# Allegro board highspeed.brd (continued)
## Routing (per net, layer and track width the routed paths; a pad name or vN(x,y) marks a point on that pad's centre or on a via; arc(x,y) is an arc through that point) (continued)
RA<1>: length 164
  TOP w0.127: v1(71.63,67.46) 71.06,68.03 65.87,68.03 65.75,67.91 50.84,67.91 48.26,70.48 U7.60 ; U4.4 v1(79.38,102.49) ; U6.4 v1(102.87,102.49) ; U3.4 v1(102.87,63.12) ; U1.4 v1(79.38,75.82) ; U2.4 v1(79.38,86.11) ; U102.4 v1(102.87,86.11) ; U101.4 v1(102.87,75.82) 103.13,75.82 103.44,75.51 103.44,69.51 103.17,69.51 103.17,69.52 v1(102.87,69.52) ; v1(78.79,63.12) 79.07,63.12 79.38,62.81 U5.4
  BOTTOM w0.127: 78.81,86.11 78.81,78.63 79.38,78.06 v1(79.38,75.82) 79.38,75.14 78.79,74.56 78.79,67.46 ; 78.81,86.11 v1(79.38,86.11) ; 78.81,86.11 78.81,99.29 79.38,99.86 v1(79.38,102.49) 79.38,106.04 78.81,106.61 78.81,108.54 80.46,110.19 101.28,110.19 102.17,109.3 102.17,106.35 102.87,105.65 v1(102.87,102.49) v1(102.87,86.11) v1(102.87,75.82) ; v1(71.63,67.46) 71.63,67.46 78.79,67.46 ; 78.79,67.46 v1(78.79,63.12) ; v1(102.87,63.12) v1(102.87,69.52)
RA<2>: length 175.6
  TOP w0.127: v1(77.54,86.11) 77.8,86.11 78.11,86.41 U2.3 ; v1(53.31,68.86) 53.31,68.86 51.16,68.86 49.53,70.48 U7.61 ; U1.3 v1(78.11,75.82) ; U101.3 v1(101.6,75.82) ; v1(101.6,63.12) U3.3 101.6,60.24 101.35,59.99 85.53,59.99 85.02,60.5 85.02,63.43 84.77,63.69 78.5,63.69 78.11,63.29 U5.3 ; U6.3 101.6,101.68 101.47,101.8 v1(101.47,102.49) 100.58,103.38 97.01,103.38 95.86,104.53 78.04,104.53 76.27,102.75 76.27,99.81 76.39,99.69 77.54,99.69 78.11,100.25 U4.3 v1(78.11,102.49) ; U102.3 v1(101.6,86.11)
  BOTTOM w0.127: v1(101.47,102.49) 101.47,97.4 101.03,96.96 101.03,86.67 v1(101.6,86.11) v1(101.6,75.82) 101.03,75.25 101.03,63.69 v1(101.6,63.12) ; v1(53.31,68.86) 55.88,71.42 76.52,71.42 77.4,72.31 77.4,73.84 78.11,74.55 v1(78.11,75.82) 78.11,78.72 77.54,79.29 v1(77.54,86.11) 77.54,100.27 78.11,100.84 v1(78.11,102.49)
RA<3>: length 149.5
  TOP w0.127: U6.2 v1(100.33,102.49) 96.24,102.49 94.53,104.2 78.55,104.2 v1(76.84,102.49) 76.84,100.96 ; v1(99.76,75.82) 100.03,75.82 100.33,75.51 U101.2 ; v1(71.04,69.39) 69.49,70.94 v1(69.49,73.66) ; 76.84,61.6 v1(76.84,63.63) ; U102.2 100.33,86.41 100.03,86.11 v1(99.76,86.11) ; U7.62 50.8,71.91 51.61,72.72 v1(52.65,72.72) ; 76.84,87.63 76.84,88.91 v1(76.27,89.48) ; 76.84,74.3 v1(76.84,75.82) ; U3.2 v1(100.33,63.63)
  BOTTOM w0.127: v1(100.33,102.49) 99.76,101.92 v1(99.76,86.11) v1(99.76,75.82) 99.76,64.2 v1(100.33,63.63) ; v1(76.84,102.49) 76.27,101.92 v1(76.27,89.48) 76.27,75.82 ; 76.27,75.82 v1(76.84,75.82) ; 76.27,75.82 74.11,73.66 v1(69.49,73.66) 68.92,74.23 53.16,74.23 52.66,73.72 52.66,72.72 v1(52.65,72.72) ; v1(71.04,69.39) 71.04,67.18 72.95,65.27 75.19,65.27 v1(76.84,63.63)
RA<4>: length 159.4
  TOP w0.127: U6.32 v1(99.06,108.97) 97.48,107.38 76.58,107.38 75.56,108.4 v1(75.56,108.97) U4.32 ; U102.32 v1(99.06,98.68) ; v1(52.09,69.67) 52.07,69.7 U7.63 ; U3.32 v1(99.06,72.64) ; U101.32 v1(99.06,82.3) ; U5.32 75.56,71.83 75,72.4 74.52,72.4 74.25,72.14 v1(73.69,72.14) ; U2.32 v1(75.56,98.68) ; U1.32 v1(75.56,82.3)
  BOTTOM w0.127: 52.09,72.14 v1(52.09,69.67) ; 52.09,72.14 52.03,72.2 52.03,73.66 54.19,75.82 74.93,75.82 75.56,76.45 v1(75.56,82.3) v1(75.56,98.68) v1(75.56,108.97) ; 52.09,72.14 v1(73.69,72.14) ; v1(99.06,108.97) v1(99.06,98.68) v1(99.06,82.3) v1(99.06,72.64)
RA<5>: length 136.7
  TOP w0.127: 76.84,83.82 v1(76.84,82.3) ; 76.84,97.16 v1(76.84,98.68) ; U3.31 v1(100.33,72.64) ; v1(76.84,77.37) v1(100.33,77.37) ; U6.31 v1(100.33,107.77) ; U7.64 v1(53.34,73.58) ; 76.84,71.12 v1(76.84,72.64) ; U101.31 v1(100.33,82.3) ; 76.84,110.49 v1(76.84,108.28) ; U102.31 v1(100.33,98.68)
  BOTTOM w0.127: v1(76.84,108.28) 76.84,108.28 77.4,108.28 77.4,101.82 76.84,101.25 v1(76.84,98.68) v1(76.84,82.3) v1(76.84,77.37) 77.4,76.8 77.4,75.13 76.84,74.56 v1(76.84,72.64) 76.27,72.64 76.2,72.71 68.34,72.71 67.45,73.59 53.35,73.59 v1(53.34,73.58) ; v1(100.33,72.64) v1(100.33,77.37) v1(100.33,82.3) v1(100.33,98.68) 100.9,99.25 100.9,107.77 100.34,107.77 v1(100.33,107.77)
RA<6>: length 140.2
  TOP w0.127: U101.30 101.6,82.6 101.91,82.3 v1(102.17,82.3) ; v1(101.6,94.11) 78.13,94.11 v1(78.11,94.08) ; U7.65 v1(54.61,68.99) ; U1.30 v1(78.11,82.3) ; U2.30 v1(78.11,98.68) ; U5.30 v1(78.11,72.64) ; U102.30 v1(101.6,95.63) ; U6.30 v1(101.6,108.97) ; U3.30 v1(101.6,72.64) ; U4.30 v1(78.11,108.97)
  BOTTOM w0.127: v1(78.11,108.97) 78.11,104.98 78.67,104.41 78.67,100.51 78.11,99.94 v1(78.11,98.68) v1(78.11,94.08) v1(78.11,82.3) 78.11,81.04 78.43,80.72 78.43,77.16 78.67,76.92 78.67,75.3 78.43,75.05 78.43,73.7 78.11,73.38 v1(78.11,72.64) 78.11,72.04 76.84,70.77 55.75,70.77 54.61,69.62 v1(54.61,68.99) ; v1(101.6,108.97) 101.6,104.65 102.17,104.08 102.17,94.11 ; 102.17,94.11 v1(102.17,82.3) 102.17,73.21 v1(101.6,72.64) ; 102.17,94.11 v1(101.6,94.11) v1(101.6,95.63)
RA<7>: length 170.4
  TOP w0.127: 102.87,81.73 90.5,81.73 90.1,82.12 90.1,84.96 89.85,85.21 88.27,85.21 87.56,85.91 85.97,85.91 85.02,84.97 85.02,82.67 84.9,82.54 82.74,82.54 82.48,82.79 82.48,84.97 82.36,85.1 79.94,85.1 79.38,84.53 U1.29 v1(79.38,82.3) ; 102.87,81.73 U101.29 ; 102.87,81.73 103.07,81.73 103.45,81.35 v1(103.45,80.75) ; U7.66 v1(55.88,68.81) ; U5.29 v1(79.38,72.64) ; U102.29 102.87,95.63 v1(103.51,95.63) ; U2.29 v1(79.38,98.68) ; U3.29 v1(102.87,72.64) ; U6.29 v1(102.87,107.77) ; U4.29 v1(79.38,108.28)
  BOTTOM w0.127: v1(102.87,72.64) 103.45,73.23 v1(103.45,80.75) 103.51,80.8 v1(103.51,95.63) 103.51,107.77 102.88,107.77 v1(102.87,107.77) ; 79.94,98.68 79.94,85.11 79.38,84.54 v1(79.38,82.3) 79.38,79.61 79.94,79.05 79.94,74.48 79.38,73.91 v1(79.38,72.64) 79.38,62.9 78.98,62.5 73.36,62.5 70.7,65.17 70.7,65.74 68.41,68.03 67.63,68.03 65.47,65.87 65.47,63.34 64.58,62.45 58.53,62.45 57.89,63.08 57.89,67.41 56.5,68.81 55.88,68.81 v1(55.88,68.81) ; 79.94,98.68 v1(79.38,98.68) ; 79.94,98.68 79.94,108.28 79.38,108.28 v1(79.38,108.28)
RA<8>: length 155.5
  TOP w0.127: U6.28 v1(104.14,108.97) ; v1(104.14,82.3) U101.28 104.14,84.53 104.71,85.1 110.3,85.1 111.06,85.86 111.06,88.81 107.12,92.75 80.66,92.75 v1(80.64,92.76) ; U3.28 v1(104.14,72.64) ; U4.28 v1(80.64,108.97) ; U1.28 v1(80.64,82.3) ; U2.28 v1(80.64,98.68) ; U7.67 v1(57.15,69.67) ; U102.28 v1(104.14,98.68) ; v1(75.89,69.6) 79.83,69.6 80.64,70.41 U5.28 v1(80.64,72.64)
  BOTTOM w0.127: v1(75.89,69.6) 75.33,69.6 74.81,70.11 57.59,70.11 v1(57.15,69.67) ; 81.21,82.3 81.21,73.21 v1(80.64,72.64) ; 81.21,82.3 81.21,92.19 v1(80.64,92.76) v1(80.64,98.68) v1(80.64,108.97) ; 81.21,82.3 v1(80.64,82.3) ; v1(104.14,108.97) v1(104.14,98.68) v1(104.14,82.3) v1(104.14,72.64)
RA<9>: length 151.9
  TOP w0.127: v1(61.98,81.36) 61.99,81.35 87.31,81.35 v1(88.27,82.3) U1.22 ; U101.22 v1(111.76,82.3) ; U4.22 v1(88.27,107.95) 94.65,107.95 98.47,111.77 111.19,111.77 111.76,111.2 U6.22 v1(111.76,108.97) ; U2.22 88.27,98.37 88.57,98.68 v1(88.72,98.68) ; U102.22 v1(111.76,98.68) ; U3.22 v1(111.76,72.64) ; U5.22 v1(88.27,72.64) ; U7.69 v1(59.69,81.36)
  BOTTOM w0.127: 88.83,82.3 v1(88.27,82.3) ; 88.83,82.3 88.83,98.68 ; 88.83,82.3 88.83,73.21 v1(88.27,72.64) ; 88.83,98.68 v1(88.72,98.68) ; 88.83,98.68 88.83,107.38 v1(88.27,107.95) ; v1(111.76,108.97) 111.19,108.4 111.19,99.25 v1(111.76,98.68) v1(111.76,82.3) v1(111.76,72.64) ; v1(59.69,81.36) 59.7,81.35 61.97,81.35 v1(61.98,81.36)
RA<10>: length 146.4
  TOP w0.127: U102.21 v1(113.03,98.68) ; v1(89.53,108.97) U4.21 89.53,111.2 90.43,112.1 112.13,112.1 113.03,111.2 U6.21 v1(113.03,108.97) ; U7.70 60.96,72.96 66.67,78.67 68.97,78.67 69.48,79.18 69.48,80.49 69.73,80.75 v1(89.53,80.75) U1.21 ; U101.21 v1(113.03,82.3) ; U3.21 v1(113.03,72.64) ; U5.21 v1(89.53,72.64) ; U2.21 v1(89.53,98.68)
  BOTTOM w0.127: v1(89.53,108.97) v1(89.53,98.68) v1(89.53,80.75) v1(89.53,72.64) ; v1(113.03,108.97) v1(113.03,98.68) v1(113.03,82.3) v1(113.03,72.64)
RA<11>: length 145.1
  TOP w0.127: U3.20 v1(114.3,72.64) ; U1.20 v1(90.81,82.3) ; U101.20 v1(114.3,82.3) ; U6.20 v1(114.3,108.97) ; v1(72.29,68.81) 63.91,68.81 62.23,70.48 U7.71 ; v1(90.81,93.5) 113.49,93.5 v1(114.3,92.69) ; U102.20 v1(114.3,98.68) ; U2.20 v1(90.81,98.68) ; v1(76.48,68.81) 81.98,68.81 82.48,69.32 82.48,72.15 82.74,72.4 87.44,72.4 87.56,72.27 87.56,70.09 87.82,69.84 90.24,69.84 90.81,70.41 U5.20 v1(90.81,72.64) ; U4.20 v1(90.81,108.97)
  BOTTOM w0.127: v1(72.29,68.81) v1(76.48,68.81) ; v1(90.81,72.64) v1(90.81,82.3) v1(90.81,93.5) v1(90.81,98.68) v1(90.81,108.97) ; v1(114.3,72.64) v1(114.3,82.3) v1(114.3,92.69) v1(114.3,98.68) v1(114.3,108.97)
RA<12>: length 147.6
  TOP w0.127: v1(115.57,105.92) U6.19 115.57,111.2 114.35,112.42 89.76,112.42 88.97,111.63 88.97,108.65 89.22,108.4 91.06,108.4 91.37,108.71 v1(92.08,108.71) U4.19 ; U5.19 v1(92.08,72.64) ; v1(92.08,77.95) 75.34,77.95 74.2,76.81 74.2,75.04 v1(73.46,74.3) ; U1.19 v1(92.08,82.3) ; U2.19 v1(92.08,98.68) ; U101.19 v1(115.57,82.3) ; U102.19 v1(115.57,98.68) ; 67.87,74.3 v1(71.25,74.3) ; U3.19 v1(115.57,72.64)
  BOTTOM w0.127: 92.64,98.68 v1(92.08,98.68) ; 92.64,98.68 92.64,82.86 v1(92.08,82.3) v1(92.08,77.95) v1(92.08,72.64) ; 92.64,98.68 92.64,108.14 v1(92.08,108.71) ; v1(115.57,105.92) 116.14,105.35 116.14,99.25 v1(115.57,98.68) v1(115.57,82.3) v1(115.57,72.64) ; v1(71.25,74.3) v1(73.46,74.3)
RA<13>: length 139
  TOP w0.127: U6.18 v1(116.84,108.97) ; U3.18 v1(116.84,72.64) ; v1(104.72,81.33) 104.73,81.33 115.87,81.33 v1(116.84,82.3) U101.18 ; v1(104.72,77.95) v1(93.34,77.95) 92.78,78.52 74.67,78.52 73.77,77.63 71.46,77.63 69.4,75.56 U7.77 ; U4.18 v1(93.34,108.97) ; U102.18 v1(116.84,98.68) ; U1.18 v1(93.34,82.3) ; U5.18 v1(93.34,72.64) ; U2.18 v1(93.34,98.68)
  BOTTOM w0.127: v1(93.34,72.64) v1(93.34,77.95) v1(93.34,82.3) v1(93.34,98.68) v1(93.34,108.97) ; v1(104.73,77.95) 104.73,81.33 v1(104.72,81.33) ; v1(116.84,108.97) v1(116.84,98.68) v1(116.84,82.3) v1(116.84,72.64)
RA<14>: length 151.4
  TOP w0.127: v1(94.16,86.11) 93.54,86.11 93.34,86.3 U2.15 ; v1(117.68,89.15) 117.04,89.15 116.84,88.95 U102.15 ; v1(117.68,99.26) 117.09,99.26 116.84,99.52 U6.15 ; 116.84,75.92 113.28,79.48 v1(94.56,79.48) 94.55,79.49 71.1,79.49 70.47,78.85 70.47,78.72 68.58,76.83 U7.78 ; 116.84,75.92 U101.15 ; 116.84,75.92 v1(117.98,75.92) ; U5.15 v1(93.34,63.63) ; v1(94.16,102.49) 93.54,102.49 93.34,102.29 U4.15 ; U3.15 v1(116.84,63.63) ; v1(93.93,69.6) 93.93,75.45 93.8,75.57 93.34,75.57 U1.15
  BOTTOM w0.127: v1(93.34,63.63) 93.93,64.21 v1(93.93,69.6) 93.93,79.48 ; v1(116.84,63.63) 117.98,64.77 v1(117.98,75.92) 117.98,85.66 117.68,85.96 v1(117.68,89.15) v1(117.68,99.26) ; 93.93,79.48 v1(94.56,79.48) ; 93.93,79.48 93.93,82.55 94.16,82.78 v1(94.16,86.11) v1(94.16,102.49)
RA<15>: length 152.9
  TOP w0.127: v1(91.51,86.11) 91.77,86.11 92.08,86.41 U2.14 ; U101.14 115.57,75.51 115.27,75.82 v1(115,75.82) ; U5.14 v1(92.08,63.63) ; U7.79 67.16,78.1 66.59,77.54 66.59,75.12 66.84,74.86 71.56,74.86 71.82,74.61 71.82,72.21 76.57,67.46 v1(91.85,67.46) v1(115.57,67.46) ; v1(91.51,75.82) 91.77,75.82 92.08,75.51 U1.14 ; U4.14 v1(92.08,102.82) ; U102.14 115.57,86.41 115.27,86.11 v1(115,86.11) ; U3.14 v1(115.57,63.63) ; U6.14 v1(115.57,102.82)
  BOTTOM w0.127: v1(115.57,63.63) v1(115.57,67.46) 115,68.03 v1(115,75.82) v1(115,86.11) 115,102.82 115.57,102.82 v1(115.57,102.82) ; v1(92.08,63.63) 92.08,64.2 91.85,64.42 v1(91.85,67.46) 91.85,69.82 91.51,70.16 v1(91.51,75.82) v1(91.51,86.11) 91.51,102.82 92.07,102.82 v1(92.08,102.82)
RCS0: length 73.2
  TOP w0.127: 81.92,76.73 102.73,76.73 102.99,77 105.16,77 105.41,76.74 U101.6 ; 81.92,76.73 81.92,74.3 ; 81.92,76.73 v1(74.93,76.73) ; U7.48 v1(42.6,79.38)
  BOTTOM w0.127: v1(42.6,79.38) 60.48,79.38 63.64,76.21 74.41,76.21 v1(74.93,76.73)
RCS1: length 93.6
  TOP w0.127: U102.6 105.41,86.92 105.98,86.35 108.39,86.35 108.52,86.48 108.52,89.51 105.85,92.18 v1(81.92,92.18) ; v1(43.18,88.95) 43.18,79.12 42.16,78.1 U7.49 ; 81.92,87.63 v1(81.92,89.33) ; v1(81.92,91.03) 72.97,91.03 70.89,88.95 62.56,88.95 v1(62.56,88.95)
  BOTTOM w0.127: v1(43.18,88.95) 43.18,88.95 62.56,88.95 v1(62.56,88.95) ; v1(81.92,89.33) v1(81.92,91.03) v1(81.92,92.18)
RCS2: length 135.4
  TOP w0.127: v1(81.56,65.25) 64.37,65.25 62.97,63.86 62.97,63.34 62.08,62.45 56,62.45 55.2,63.24 55.2,63.81 53.8,65.2 38.88,65.2 36.72,67.36 36.72,75.45 38.1,76.83 U7.50 ; 81.92,100.96 81.92,101.68 83.87,103.63 v1(90.17,103.63) ; U3.6 v1(105.41,63.12)
  BOTTOM w0.127: v1(105.41,63.12) 104.84,62.55 92.26,62.55 89.84,64.96 89.84,66.23 ; 89.84,66.23 90.17,66.55 v1(90.17,103.63) ; 89.84,66.23 81.96,66.23 81.56,65.83 v1(81.56,65.25)
RCS3: length 125.4
  TOP w0.127: v1(98.37,65.66) v1(83.06,65.66) 82.45,65.66 82.21,65.9 39.21,65.9 37.94,67.17 37.94,67.92 38.73,68.71 39.94,68.71 41.21,69.98 41.21,73.88 39.52,75.56 U7.51 ; v1(98.37,104.22) 103.82,104.22 105.41,102.63 U6.6 ; 81.92,61.6 v1(81.92,63.12)
  BOTTOM w0.127: v1(98.37,104.22) 98.38,104.21 98.38,65.66 v1(98.37,65.66) ; v1(83.06,65.66) 83.06,64.26 v1(81.92,63.12)
RD<0>: length 94.1
  TOP w0.127: U7.81 61.8,80.64 61.41,81.04 61.41,88.71 64.07,91.37 70.22,91.37 73.49,94.65 82.2,94.65 v1(83.19,95.63) U2.26 ; U4.26 v1(83.19,108.97) ; v1(83.19,106.53) 104.01,106.53 106.68,109.19 U6.26 ; U1.26 v1(83.19,85.34)
  BOTTOM w0.127: v1(83.19,108.97) v1(83.19,106.53) 83.75,105.96 83.75,95.63 ; 83.75,95.63 83.75,85.91 v1(83.19,85.34) ; 83.75,95.63 v1(83.19,95.63)
RD<1>: length 76.6
  TOP w0.127: U6.23 110.49,109.12 107.31,105.94 v1(87,105.94) ; U7.82 70.79,81.91 71.43,82.56 74.09,82.56 74.92,81.73 86.2,81.73 87,82.52 v1(87,85.34) ; 87,97.16 87,95.94 87.3,95.63 v1(87.56,95.63) ; 87,110.49 v1(87,108.97)
  BOTTOM w0.127: v1(87,108.97) v1(87,105.94) 87.56,105.37 v1(87.56,95.63) 87.56,87.7 87,87.13 v1(87,85.34)
RD<2>: length 100
  TOP w0.127: 87,74.3 v1(87,76.15) ; 87,89.79 v1(92.08,89.79) ; 87,89.79 v1(87,89.15) 87,87.63 ; 87,89.79 86.73,90.05 75.98,90.05 73.95,88.02 73.95,84.84 72.3,83.19 U7.83 ; U6.10 110.49,102.26 111.28,103.06 113.98,103.06 114.87,102.17 114.87,95.95 113.98,95.06 92.83,95.06 92.64,95.25 v1(92.08,95.25) ; 87,100.96 v1(87,99.44)
  BOTTOM w0.127: v1(87,76.15) 86.43,76.15 86.43,88.58 v1(87,89.15) v1(87,99.44) ; v1(92.08,89.79) v1(92.08,95.25)
RD<3>: length 79.3
  TOP w0.127: v1(83.19,99.44) U4.7 83.19,101.68 84.57,103.06 90.48,103.06 91.37,102.17 91.37,99.94 91.63,99.69 106.11,99.69 106.68,100.25 U6.7 ; v1(83.19,89.33) U2.7 83.19,86.92 84.05,86.06 85.04,86.06 v1(85.04,86.05) ; U1.7 v1(83.19,76) ; U7.84 v1(70.26,84.45) ; v1(74.73,93.34) v1(83.19,93.34)
  BOTTOM w0.127: v1(74.73,93.34) 74.73,93.34 74.73,88.92 v1(70.26,84.45) ; v1(83.19,99.44) 82.62,98.87 82.62,94.92 83.19,94.35 v1(83.19,93.34) v1(83.19,89.33) ; v1(85.04,86.05) 85.04,84.77 83.19,82.92 v1(83.19,76)
RD<4>: length 105.5
  TOP w0.127: 105.98,72.64 105.98,77.58 104.71,78.85 84.09,78.85 83.93,79 71.46,79 v1(71.37,78.92) ; 105.98,72.64 105.98,69.35 105.58,68.95 84.07,68.95 83.19,69.84 U5.26 ; 105.98,72.64 v1(106.68,72.64) U3.26 ; U102.26 v1(106.68,95.63) ; U101.26 v1(106.68,82.3) ; U7.1 v1(69.39,85.72)
  BOTTOM w0.127: v1(69.39,85.72) 69.39,83.03 71.37,81.05 v1(71.37,78.92) ; v1(106.68,95.63) v1(106.68,82.3) v1(106.68,72.64)
RD<5>: length 115.1
  TOP w0.127: v1(72.16,83.87) 72.16,83.87 72.16,84.58 69.75,86.99 U7.2 ; 92.64,75.9 92.16,76.39 87.96,76.39 87.56,75.99 87.56,73.14 87.44,73.02 81.47,73.02 81.21,73.27 81.21,76.13 80.96,76.39 76.53,76.39 76.13,75.99 76.13,73.14 76.01,73.02 73.81,73.02 72.16,74.67 72.16,76.78 v1(72.16,76.78) ; 92.64,75.9 95.14,75.9 v1(95.15,75.89) ; 92.64,75.9 92.64,69.91 92.25,69.51 87.25,69.51 87,69.77 87,71.12 ; U101.23 v1(110.49,82.3) ; v1(95.15,68.22) 108.9,68.22 110.49,69.81 U3.23 v1(110.49,72.64) ; U102.23 v1(110.49,95.63)
  BOTTOM w0.127: v1(72.16,76.78) 72.16,76.78 72.16,83.87 v1(72.16,83.87) ; v1(95.15,68.22) v1(95.15,75.89) ; 111.06,82.3 111.06,73.21 v1(110.49,72.64) ; 111.06,82.3 v1(110.49,82.3) ; 111.06,82.3 111.06,95.06 v1(110.49,95.63)
RD<6>: length 104.2
  TOP w0.127: U101.10 v1(110.49,75.82) ; U7.3 71.69,88.27 73.8,90.38 92.39,90.38 92.64,90.13 92.64,86.43 93.53,85.54 109.92,85.54 v1(110.49,86.11) U102.10 ; 87,61.6 87,60.88 87.56,60.32 100.77,60.32 100.9,60.44 100.9,63.29 101.3,63.69 109.92,63.69 v1(110.49,63.12) U3.10
  BOTTOM w0.127: 109.92,75.82 109.92,85.54 v1(110.49,86.11) ; 109.92,75.82 109.92,63.69 v1(110.49,63.12) ; 109.92,75.82 v1(110.49,75.82)
RD<7>: length 99.6
  TOP w0.127: v1(106.68,63.12) U3.7 106.68,60.88 105.46,59.66 84.41,59.66 83.19,60.88 U5.7 ; U102.7 106.68,89.89 ; 106.68,89.89 104.97,91.6 71.78,91.6 69.71,89.53 U7.4 ; 106.68,89.89 v1(107.26,89.89) ; v1(107.25,75.82) 106.98,75.82 106.68,75.51 U101.7
  BOTTOM w0.127: v1(107.26,89.89) 107.27,89.89 107.27,76.4 107.25,76.39 v1(107.25,75.82) 107.25,63.69 v1(106.68,63.12)
RDY: length 33.9
  TOP w0.127: v1(41.28,59.16) 41.14,59.02 15.62,59.02 14.73,59.91 14.73,60.07 13.84,60.96 J3.50
  BOTTOM w0.127: 41.28,63.5 v1(41.28,59.16)
RESET: length 75.2
  TOP w0.127: U7.15 v1(62.23,98.73)
  BOTTOM w0.127: J3.53 13.75,69.63 18.68,69.63 21.35,72.3 21.35,80.59 22.5,81.75 22.5,86.9 24.74,89.14 24.74,91.91 24.97,92.15 24.97,94.52 30.05,99.6 61.36,99.6 v1(62.23,98.73)
RWE: length 174.4
  TOP w0.127: U5.11 v1(88.27,63.63) ; U101.11 111.76,75.72 v1(112.45,76.4) ; U7.57 44.45,67.72 44.7,67.46 v1(68.1,67.46) ; U4.11 v1(88.27,102.49) ; v1(112.45,89.26) 111.86,89.26 111.76,89.16 U102.11 ; U6.11 v1(111.76,102.49) ; U2.11 v1(88.27,86.11) ; U3.11 v1(111.76,63.12) ; U1.11 v1(88.27,75.82)
  BOTTOM w0.127: 87.7,75.82 v1(88.27,75.82) ; 87.7,75.82 87.7,85.54 v1(88.27,86.11) 88.27,92.18 88.15,92.29 88.15,101.81 88.27,101.92 v1(88.27,102.49) ; 87.7,75.82 83.02,71.15 82.64,71.15 80.99,69.49 80.99,64.45 81.21,64.23 81.21,62.55 81.54,62.22 ; v1(68.1,67.46) 68.1,66.78 73.3,61.57 80.89,61.57 81.54,62.22 ; 81.54,62.22 88.27,62.22 ; 88.27,62.22 110.86,62.22 v1(111.76,63.12) 112.45,63.8 v1(112.45,76.4) v1(112.45,89.26) 112.45,101.8 v1(111.76,102.49) ; 88.27,62.22 v1(88.27,63.63)
SEL: length 41.9
  TOP w0.127: U7.13 64.77,99.54 62.75,97.52 62.68,97.52 59.12,93.96 59.12,69.49 60.14,68.48 v1(61.29,68.48)
  BOTTOM w0.127: v1(61.29,68.48) 64.14,65.63 U17.14
UNNAMED_1_ACT574_I1_Q0: length 52.1
  TOP w0.127: U1_1.12 87.97,25.82 86.11,23.96 86.11,23.95 85.48,23.31 71.42,23.31 65.61,29.13 62.28,29.13 59,32.42 49.19,32.42 44.61,36.99 U20.19
UNNAMED_1_ACT574_I1_Q1: length 51.2
  TOP w0.127: U20.18 45.88,36.91 49.44,33.35 59.96,33.35 63.86,29.46 65.88,29.46 71.69,23.64 84.57,23.64 85.46,24.53 85.46,24.58 87.97,27.09 U1_1.13
UNNAMED_1_ACT574_I1_Q2: length 50.1
  TOP w0.127: U1_1.14 87.97,28.36 83.82,24.21 83.82,24.17 83.62,23.97 72.92,23.97 67.11,29.78 64.56,29.78 60.29,34.06 50.08,34.06 47.15,36.98 U20.17
UNNAMED_1_ACT574_I1_Q3: length 57.7
  TOP w0.127: U20.16 48.42,39.02 49.7,40.3 87.59,40.3 93.05,34.83 93.05,30.27 92.42,29.63 U1_1.15 88.29,29.63
UNNAMED_1_ACT574_I1_Q4: length 43.9
  TOP w0.127: U1_1.16 86.25,30.9 85.67,31.48 76.66,31.48 75.35,30.17 65.22,30.17 60.68,34.71 51.98,34.71 49.69,37 U20.15
UNNAMED_1_ACT574_I1_Q5: length 44
  TOP w0.127: U20.14 50.96,39.02 51.53,39.59 52.68,39.59 52.8,39.46 52.8,37.18 53.56,36.42 60.39,36.42 61.47,37.5 75.21,37.5 76.15,36.56 82.57,36.56 86.96,32.17 U1_1.17
UNNAMED_1_ACT574_I1_Q6: length 48.3
  TOP w0.127: U20.13 52.23,37.59 51.67,37.03 50.52,37.03 50.39,37.15 50.39,39.52 50.79,39.91 53.68,39.91 54.07,39.52 54.07,37.33 54.33,37.08 56.22,37.08 56.98,37.83 76.84,37.83 77.78,36.89 83.79,36.89 87.24,33.44 U1_1.18
UNNAMED_1_ACT574_I1_Q7: length 40.1
  TOP w0.127: U1_1.19 87.97,34.71 86.02,36.66 86.02,36.71 85.52,37.22 79.71,37.22 78.19,38.73 60.03,38.73 v1(60.02,38.73) ; U20.12 53.5,37 53.76,36.75 59.76,36.75 v1(60.02,37.01)
  BOTTOM w0.127: v1(60.02,37.01) 60.02,37.01 v1(60.02,38.73)
UNNAMED_1_ACT574_I2_Q0: length 57.4
  TOP w0.127: 89,5.12 87.59,5.12 82.89,9.82 82.89,15.69 82.05,16.53 78.13,16.53 75.79,18.88 48.89,18.88 44.07,23.7 U21.19
UNNAMED_1_ACT574_I2_Q1: length 57
  TOP w0.127: 45.34,25.07 45.34,23.7 49.66,19.39 82.78,19.39 83.54,18.62 83.54,10.45 87.61,6.39 89,6.39
UNNAMED_1_ACT574_I2_Q2: length 54.7
  TOP w0.127: U21.17 46.61,23.78 50.67,19.71 82.98,19.71 83.87,18.82 83.87,11.47 87.68,7.66 89,7.66
UNNAMED_1_ACT574_I2_Q3: length 59.2
  TOP w0.127: 88.59,8.93 90.75,8.93 90.9,9.08 90.9,18.38 86.95,22.33 65.66,22.33 61.31,26.68 48.78,26.68 47.88,25.78 47.88,25.07
UNNAMED_1_ACT574_I2_Q4: length 50
  TOP w0.127: U21.15 49.15,23.72 52.83,20.04 83.18,20.04 84.2,19.02 84.2,13.63 87.62,10.2 89,10.2
UNNAMED_1_ACT574_I2_Q5: length 51.9
  TOP w0.127: 50.42,25.07 50.42,25.78 50.99,26.35 60.41,26.35 65.08,21.68 85.8,21.68 90.4,17.08 90.4,11.88 89.99,11.47 88.59,11.47
UNNAMED_1_ACT574_I2_Q6: length 45.3
  TOP w0.127: 89,12.74 87.57,12.74 84.52,15.79 84.52,19.35 83.38,20.49 54.86,20.49 51.69,23.67 U21.13
UNNAMED_1_ACT574_I2_Q7: length 43.2
  TOP w0.127: 89,14.01 87.62,14.01 84.95,16.68 84.95,19.62 83.55,21.02 55.63,21.02 52.96,23.69 U21.12
UNNAMED_1_CAP_I33_A_1: length 12.8
  TOP w0.127: 74.37,32.17 74.37,35.33 L1_1.2 ; 74.37,32.17 73.78,31.58 C2_1.1 ; 74.37,32.17 U1_1.4
UNNAMED_1_CAP_I33_A_2: length 12.8
  TOP w0.127: C2_2.1 74.08,10.88 74.67,11.47 ; L1_2.2 74.67,14.63 74.67,11.47 ; 74.67,11.47 U1_2.4
UNNAMED_1_CAP_I67_A: length 2.2
  TOP w0.127: C21.1 R11.2
UNNAMED_1_CAP_I68_A: length 2.2
  TOP w0.127: C22.1 R12.2
UNNAMED_1_CAP_I69_A: length 2.2
  TOP w0.127: C23.1 R13.2
UNNAMED_1_CAP_I70_A: length 2.2
  TOP w0.127: C24.1 R14.2
UNNAMED_1_CAP_I71_A: length 2.2
  TOP w0.127: C25.1 R15.2
UNNAMED_1_CAP_I72_A: length 2.2
  TOP w0.127: C26.1 R16.2
UNNAMED_1_CAP_I73_A: length 2.2
  TOP w0.127: C27.1 R17.2
UNNAMED_1_CAP_I74_A: length 2.2
  TOP w0.127: C28.1 R18.2
UNNAMED_1_DG419_I6_D_1: length 10.5
  TOP w0.5: U2_1.1 103.41,33.69 99.6,29.88
UNNAMED_1_DG419_I6_D_2: length 10.5
  TOP w0.5: 108.82,12.98 103.7,12.98 U3_2.2
UNNAMED_1_DG419_I6_S1_1: length 6.4
  TOP w0.127: R2_1.2 109.91,27.64 110.88,28.61 110.88,30.38 108.84,32.41 U2_1.2
UNNAMED_1_DG419_I6_S1_2: length 6.4
  TOP w0.127: R2_2.2 110.21,6.94 111.18,7.91 111.18,9.68 109.14,11.71 108.82,11.71
UNNAMED_1_DG419_I6_S2_1: length 3.5
  TOP w0.127: R1_1.2 116.44,32.57 115.32,33.69 U2_1.8
UNNAMED_1_DG419_I6_S2_2: length 3.5
  TOP w0.127: R1_2.2 116.74,11.87 115.62,12.98 U2_2.8
UNNAMED_1_DG419_I6_VL_1: length 67.7
  TOP w0.127: U1_1.8 77.19,27.09 77,27.28 ; 78.13,30.9 77.25,30.9 77,30.65 77,27.28 ; 78.13,30.9 77.81,30.57 77.81,29.27 78.13,28.94 90.14,28.94 91.2,27.88 91.2,25.77 94.12,22.85 114.34,22.85 115.86,24.38 115.86,28.66 ; 78.13,30.9 U1_1.5 ; 115.86,28.66 115.53,28.99 113.48,28.99 ; 115.86,28.66 116.5,29.3 R1_1.1 ; 77,27.28 L2_1.2 ; 113.48,29.88 113.48,28.99 ; 113.48,28.99 113.48,28.92 112.2,27.64 R2_1.1
UNNAMED_1_DG419_I6_VL_2: length 64.2
  TOP w0.127: 77.5,8.28 77.5,6.58 ; 77.5,8.28 77.54,8.24 80.63,8.24 80.64,8.23 82.35,8.23 83,7.58 83,5.38 86.11,2.28 109.76,2.28 115.1,7.61 115.1,8.29 ; 77.5,8.28 77.5,10.08 77.62,10.2 U1_2.5 ; 77.5,6.58 77.69,6.39 U1_2.8 ; 77.5,6.58 L2_2.2 ; 115,8.62 115,8.92 114.75,9.18 U2_2.5 ; 115,8.62 115.1,8.52 115.1,8.29 ; 115,8.62 115,8.4 113.48,6.88 R2_2.1 ; R1_2.1 116.8,8.49 116.6,8.29 115.1,8.29
UNNAMED_1_TLC5602_I31_AOUT_1: length 19.6
  TOP w0.127: v1(92.2,30.23) 87.24,30.23 86.64,29.63 U1_1.6
  BOTTOM w0.127: v1(92.2,30.23) 93.8,30.23 95.24,31.67 96.75,31.67 U3_1.3
UNNAMED_1_TLC5602_I31_AOUT_2: length 28.9
  TOP w0.127: v1(94.49,3.17) 86.88,3.17 84.4,5.65 84.4,7.48 82.95,8.93 U1_2.6
  BOTTOM w0.127: v1(94.49,3.17) 94.49,9.07 96.39,10.97 97.05,10.97 U3_2.3
UNNAMED_2_EPF8282A_I1_VCLKC: length 57.7
  TOP w0.127: v1(41.5,90.78) 41.5,91.95 40.11,93.34 U7.37
  BOTTOM w0.127: v1(41.5,90.78) 41.5,78.87 42.01,78.36 42.11,78.36 43.7,76.78 43.7,67.86 44.84,66.71 47.53,66.71 50.32,63.93 50.32,47.03 51.91,45.44 52.96,45.44 R5.1
UNNAMED_3_ACT574_I6_Q0: length 7.9
  TOP w0.127: R20.1 148.88,83.86 U24.19
UNNAMED_3_ACT574_I6_Q1: length 7.6
  TOP w0.127: 144.74,82.59 149.64,82.59 R21.1
UNNAMED_3_ACT574_I6_Q2: length 7.3
  TOP w0.127: R22.1 150.4,81.32 U24.17
UNNAMED_3_ACT574_I6_Q3: length 7
  TOP w0.127: R23.1 151.16,80.05 U24.16
UNNAMED_3_ACT574_I6_Q4: length 7
  TOP w0.127: R24.1 151.16,78.78 U24.15
UNNAMED_3_ACT574_I6_Q5: length 7.3
  TOP w0.127: R25.1 150.4,77.52 144.74,77.52
UNNAMED_3_ACT574_I6_Q6: length 7.6
  TOP w0.127: U24.13 148.67,76.24 150.58,74.34 R26.1
UNNAMED_3_ACT574_I6_Q7: length 7.9
  TOP w0.127: U24.12 148.88,74.97 R27.1
UNNAMED_3_MN3102_I89_OUT: length 3.5
  TOP w0.127: U22.7 97.23,51.31 R19.1
V+12: length 261.7
  TOP w0.4: v1(94.08,23.75) 94.07,23.76 94.07,34.75 95.6,36.28 C3_1.1 95.6,37.92 91.79,41.73 57.41,41.73 54.86,44.29 41.71,44.29 38.97,41.55 38.97,31.7 32.49,25.23 17.63,25.23 16.11,26.75 v1(2.21,26.75) ; 98.1,3.65 103.11,3.65 106.16,6.7 106.16,6.82 108.51,9.18 108.82,9.18 ; 98.1,3.65 U3_2.7 ; 98.1,3.65 95.87,3.65 94.37,5.15 94.37,14.05 95.9,15.58 C3_2.1 95.9,15.98 94.92,16.96 94.92,19.38 v1(95.63,20.09) ; U3_1.7 98.7,24.64 103.02,24.64 106.42,28.04 106.42,28.09 108.21,29.88 108.52,29.88 ; J3.63 J3.64
  BOTTOM w0.4: 95.63,23.42 97.17,23.42 97.8,24.06 U3_1.7 ; 95.63,23.42 v1(95.63,20.09) ; 95.63,23.42 95.3,23.75 v1(94.08,23.75) ; v1(2.21,26.75) 2.21,90.85 6.53,95.17 11.35,95.17 J3.64
VCLKA: length 148.4
  TOP w0.127: 89,3.85 90.67,3.85 91.6,4.78 91.6,20.75 89.14,23.21 ; v1(55.37,39.78) 54.77,39.78 U20.11 ; v1(56.31,28.68) 63.52,28.68 65.17,27.02 65.17,26.95 69.23,22.89 88.81,22.89 89.14,23.21 ; v1(55.32,69.55) 55.31,69.56 55.31,79.69 44.97,90.03 44.97,101.4 44.46,101.91 43.19,101.91 42.43,101.15 42.43,99.06 40.52,97.16 U7.34 ; 89.14,23.21 89.14,24.11 U1_1.11
  BOTTOM w0.127: v1(55.32,69.55) 55.31,69.53 55.31,40.36 55.37,40.3 v1(55.37,39.78) 56.32,38.83 56.32,28.68 v1(56.31,28.68)
VCLKC: length 32.5
  TOP w0.127: U21.11 v1(54.23,23.16)
  BOTTOM w0.127: v1(54.23,23.16) 52.74,24.65 52.74,35.15 52.44,35.45 52.44,41.43 54.36,43.36 54.36,49.58 53.97,49.98 53.36,49.98 52.96,49.58 R5.2
VD<0>: length 327
  TOP w0.127: U19.2 v1(44.07,41.02) ; U20.2 44.61,30.62 v1(44.6,30.63) ; U21.2 v1(44.07,17.96) 44.06,17.97 42.55,17.97 40.77,16.19 R18.1 ; v1(69.98,92.28) 72.68,94.98 80.2,94.98 81.21,95.99 81.21,98.18 81.47,98.44 83.63,98.44 83.75,98.31 83.75,95.31 84.39,94.68 117.47,94.68 120.64,91.5 120.64,91.48 128.26,83.86 U24.2 139.49,83.86 143.19,87.56 152.38,87.56 152.5,87.43 152.5,62.14 148.73,58.36 148.73,38.35 157.42,29.65 189.76,29.65 195.09,24.32 195.09,23.09 194.53,22.52 U25.2 ; U7.39 v1(37.29,90.8)
  BOTTOM w0.127: 44.3,30.63 v1(44.6,30.63) ; 44.3,30.63 44.3,18.76 44.07,18.53 v1(44.07,17.96) ; 44.3,30.63 44.03,30.63 44.03,40.42 44.07,40.45 v1(44.07,41.02) 42.85,42.24 41.75,42.24 36.16,47.83 36.16,89.68 v1(37.29,90.8) 37.86,91.37 37.86,91.39 38.75,92.27 69.97,92.27 v1(69.98,92.28)
VD<1>: length 285.6
  TOP w0.127: 45.34,15.88 v1(45.34,17.4) 44.77,17.4 44.64,17.27 44.64,14.75 44.24,14.35 43.72,14.35 42.93,13.56 R17.1 ; 45.34,42.55 v1(45.34,41.02) ; v1(70.05,80.16) 121.32,80.16 123.89,82.73 134.12,82.73 134.26,82.59 143.07,82.59 143.07,82.25 v1(143.08,82.24) ; v1(45.87,30.66) 45.88,30.65 U20.3 ; v1(188.26,21.51) 188.26,21.25 U25.3 ; U7.40 v1(40.33,89.53)
  BOTTOM w0.127: v1(70.05,80.16) 64.44,85.78 64.44,88 61.14,91.3 41.22,91.3 40.33,90.41 v1(40.33,89.53) 38.51,87.71 38.51,76.22 39.79,74.94 39.79,49.44 45.34,43.89 v1(45.34,41.02) 45.34,36.13 45.57,35.9 45.57,30.66 ; 45.57,30.66 v1(45.87,30.66) ; 45.57,30.66 45.57,30.06 45.34,29.83 v1(45.34,17.4) ; v1(143.08,82.24) 159.75,65.57 159.75,55.12 188.26,26.61 v1(188.26,21.51)
VD<2>: length 292
  TOP w0.127: v1(187.1,20.24) 187.1,19.98 U25.4 ; v1(40.36,59.97) 40.37,59.98 65.21,59.98 65.85,59.33 119.36,59.33 124.31,64.29 124.31,74.58 124.87,75.14 124.87,75.62 124.63,75.86 124.63,76.25 130.78,82.41 132.56,82.41 133.65,81.32 U24.4 140.49,81.32 v1(143.03,78.79) ; U21.4 46.61,14.35 ; 46.61,14.35 45.88,14.35 45.08,13.56 R16.1 ; 46.61,14.35 v1(47.14,14.35) ; v1(47.14,30.63) 47.15,30.62 U20.4 ; U7.41 v1(40.92,88.27) ; U19.4 v1(46.61,41.02)
  BOTTOM w0.127: v1(47.14,14.35) v1(47.14,30.63) 47.14,35.19 46.61,35.72 v1(46.61,41.02) 46.61,48.01 42.33,52.29 42.33,56.93 40.36,58.89 v1(40.36,59.97) 40.22,60.11 40.22,79.1 40.92,79.79 v1(40.92,88.27) ; v1(187.1,20.24) 187.1,26.28 159.43,53.95 159.43,62.39 v1(143.03,78.79)
VD<3>: length 306.5
  TOP w0.127: U24.5 134.02,80.05 v1(134.01,80.06) ; U7.42 v1(37.29,86.99) ; v1(39.17,66.9) 39.76,66.31 115.73,66.31 122.08,72.66 122.08,76.59 123.19,77.7 123.19,77.97 124,78.78 v1(125.1,78.78) ; v1(139.19,54.56) 139.19,54.29 139.5,53.98 U8.4 141.53,53.98 143.08,52.44 143.08,39.65 155.78,26.95 177.68,26.95 185.92,18.71 U25.5 ; 47.88,42.55 v1(47.88,40.87) ; R15.1 47.37,13.41 47.88,13.92 v1(47.88,17.73) ; U20.5 48.42,30.62 v1(48.41,30.63) 41.66,37.39 v1(41.66,43.16)
  BOTTOM w0.127: v1(47.88,17.73) 48.18,17.73 48.18,17.73 48.41,17.73 v1(48.41,30.63) 48.41,39.77 47.88,40.3 v1(47.88,40.87) ; v1(37.29,86.99) 38.18,86.1 38.18,72.47 39.17,71.49 v1(39.17,66.9) 37.68,65.42 37.68,47.13 v1(41.66,43.16) ; v1(125.1,78.78) 126.38,80.06 v1(134.01,80.06) 134.01,76.81 134.19,76.62 134.19,75.88 134.01,75.69 134.01,59 138.45,54.56 139.19,54.56 v1(139.19,54.56)
VD<4>: length 313.9
  TOP w0.127: v1(123.34,64.21) 76.41,64.21 73.85,61.65 v1(54.23,61.65) ; U21.6 49.15,14.35 ; 49.15,14.35 v1(49.68,14.35) ; 49.15,14.35 49.15,13.79 49.53,13.41 R14.1 ; v1(139.19,55.47) 139.19,55.47 139.53,55.47 139.53,55.26 U8.3 141.53,55.26 144.06,52.72 144.06,41.05 156.76,28.35 177.89,28.35 186.95,19.28 194.97,19.28 195.09,19.16 195.09,18.01 194.53,17.45 U25.6 ; U24.6 136.82,78.78 137.04,78.56 v1(137.74,78.56) ; U19.6 v1(49.15,41.02) ; U7.43 39.52,85.72 41.81,88.02 41.81,88.5 42.83,89.52 43.5,89.52 43.75,89.27 43.75,77.82 45.03,76.53 v1(45.03,68.05) ; U20.6 49.69,30.62 v1(49.68,30.63)
  BOTTOM w0.127: v1(123.34,64.21) 119.7,67.85 119.7,77.4 123.26,80.96 135.34,80.96 v1(137.74,78.56) 137.74,56.27 138.53,55.47 139.19,55.47 v1(139.19,55.47) ; v1(49.68,14.35) v1(49.68,30.63) 49.72,30.67 49.72,40.45 v1(49.15,41.02) 51.93,43.8 52.28,43.8 53.94,45.45 53.94,47.2 53.54,47.59 52.16,47.59 51.66,48.1 51.66,51.59 52.81,52.75 52.81,60.87 ; 52.81,60.87 53.46,60.87 v1(54.23,61.65) ; 52.81,60.87 52.49,61.2 52.49,64.7 49.14,68.05 45.03,68.05 v1(45.03,68.05)
VD<5>: length 306.2
  TOP w0.127: 50.42,15.88 50.42,14.66 50.72,14.35 v1(50.95,14.35) 51.56,13.74 R13.1 ; v1(50.7,40.97) 50.42,41.25 50.42,42.55 ; v1(38.51,67.49) 41.72,67.49 42.33,66.88 v1(57.3,66.88) 57.31,66.88 115.79,66.88 121.51,72.59 121.51,77.16 v1(121.51,77.16) ; 135.54,77.52 132.71,77.52 132.71,77.47 132.71,77.47 v1(132.71,77.16) ; v1(183.87,16.43) 183.88,16.42 183.88,16.18 193.81,16.18 ; U20.7 50.96,30.63 v1(50.95,30.63) 52.12,31.8 57.45,31.8 v1(57.45,31.8) ; U7.44 v1(37.29,84.45)
  BOTTOM w0.127: v1(50.7,40.97) 50.71,40.96 50.71,30.87 v1(50.95,30.63) v1(50.95,14.35) ; v1(183.87,16.43) 183.87,20.51 182.92,21.46 182.92,21.5 182.58,21.83 182.55,21.83 177.1,27.28 167,27.28 150.3,43.98 138.7,43.98 132.8,49.88 132.8,74.95 133.87,76.02 133.87,76.49 133.19,77.16 v1(132.71,77.16) 132.71,77.16 121.52,77.16 v1(121.51,77.16) ; v1(57.3,66.88) 57.3,65.66 57.57,65.4 57.57,31.91 v1(57.45,31.8) ; v1(37.29,84.45) 37.86,83.89 37.86,67.49 v1(38.51,67.49)
VD<6>: length 301.3
  TOP w0.127: U24.8 133.3,76.24 v1(133.3,76.25) ; R12.1 53.72,13.63 53.32,14.02 53.08,14.02 52.29,14.82 v1(52.29,17.4) 51.99,17.4 51.69,17.09 U21.8 ; U7.45 v1(36.73,83.19) ; v1(52.22,30.63) 52.23,30.62 U20.8 ; v1(182.35,21.26) 182.35,17.06 184.51,14.91 U25.8 ; v1(51.69,40.97) U19.8 51.69,43.26 51.12,43.83 47.42,43.83 47.29,43.7 47.29,40.29 v1(47.3,40.28) ; v1(36.73,62.23) v1(42.67,62.23) 54.82,62.23 54.92,62.12 73.52,62.12 76.07,64.67 114.62,64.67 122.75,72.8 122.75,74.25 124.06,75.56 124.12,75.56 v1(124.3,75.38)
  BOTTOM w0.127: v1(36.73,83.19) 36.72,83.17 36.72,62.24 v1(36.73,62.23) ; v1(47.3,40.28) 47.29,40.29 47.29,50.95 46.15,52.09 46.1,52.09 42.67,55.52 v1(42.67,62.23) ; v1(52.29,17.4) 52.29,17.97 52.22,18.03 v1(52.22,30.63) 52.22,32.9 51.69,33.43 v1(51.69,40.97) ; v1(124.3,75.38) 125.17,76.24 133.29,76.24 v1(133.3,76.25) 133.3,75.91 132.47,75.08 132.47,49.74 139.14,43.08 149.6,43.08 165.73,26.95 176.96,26.95 182.35,21.57 v1(182.35,21.26)
VD<7>: length 301.3
  TOP w0.127: U21.9 52.96,15.16 53.56,14.56 54.98,14.56 v1(55.88,13.66) R11.1 ; v1(45.26,58.83) 45.52,58.57 62.53,58.57 62.65,58.45 ; 62.65,58.45 124.71,58.45 v1(124.71,58.45) ; 62.65,58.45 62.65,54.63 v1(62.66,54.61) ; v1(165.6,22.28) 165.6,22.18 174.14,13.64 193.81,13.64 ; v1(42.32,77.42) 37.78,77.42 37.53,77.67 37.53,81.35 38.1,81.91 U7.46 ; v1(53.49,30.63) 53.5,30.62 U20.9 ; U19.9 v1(52.96,40.97) ; U24.9 132.75,74.97 132.54,75.18 v1(130.2,75.18)
  BOTTOM w0.127: 55.88,28.14 55.4,28.14 53.49,30.05 v1(53.49,30.63) 53.49,37.22 52.96,37.75 v1(52.96,40.97) ; 55.88,28.14 v1(55.88,13.66) ; 55.88,28.14 56.52,28.14 58.68,30.3 58.68,50.63 v1(62.66,54.61) ; v1(165.6,22.28) 150.2,37.68 150.2,39.28 148.2,41.28 130.2,41.28 128.68,42.8 128.68,58.45 ; 128.68,58.45 124.72,58.45 v1(124.71,58.45) ; 128.68,58.45 128.68,74.26 129.6,75.18 v1(130.2,75.18) ; v1(42.32,77.42) 42.33,77.41 42.33,66.47 43.6,65.2 43.61,65.2 45.26,63.55 45.26,58.83 v1(45.26,58.83)
VREF: length 31.4
  TOP w0.4: v1(61.62,18.29) 63.39,18.29 L1_2.1 ; v1(60.35,35.31) 64.23,35.31 L1_1.1 ; R10.1 61.62,22.08 v1(61.62,23.49)
  BOTTOM w0.4: v1(60.35,35.31) 60.36,35.3 60.36,24 60.86,23.49 v1(61.62,23.49) v1(61.62,18.29)
WAIT: length 57.6
  TOP w0.127: v1(28.37,75.51) 32.88,75.51 34.15,76.78 34.15,95.12 37.45,98.42 U7.33
  BOTTOM w0.127: J3.51 27.11,63.5 28.38,64.77 28.38,75.5 v1(28.37,75.51)
WSTAT: length 27.7
  TOP w0.127: U19.11 54.23,52.45 53.42,53.26 v1(47.57,53.26) ; U7.56 v1(43.18,69.67)
  BOTTOM w0.127: v1(43.18,69.67) 43.18,67.76 45.08,65.86 45.54,65.86 47.57,63.83 v1(47.57,53.26)

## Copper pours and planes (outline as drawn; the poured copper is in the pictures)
AGND on BOTTOM: 63.6,25.38 63.6,36.38 67.6,40.38 103.6,40.38 108.6,35.38 108.6,24.38 107.6,23.38 103.6,23.38 103.6,30.38 101.6,32.38 93.6,32.38 91.6,30.38 91.6,26.38 87.6,22.38 66.6,22.38
AGND on BOTTOM: 63.9,4.68 63.9,15.68 67.9,19.68 103.9,19.68 108.9,14.68 108.9,3.68 107.9,2.68 103.9,2.68 103.9,9.68 101.9,11.68 93.9,11.68 91.9,9.68 91.9,5.68 87.9,1.68 66.9,1.68
GND on GND (solid shape): 120.9,21.08 119.5,21.08 119.5,22.88 120.9,22.88
GND on GND: 23.65,1.9 23.5,2.06 23.5,6.99 2.06,6.99 1.9,7.14 1.9,107.16 2.06,107.31 23.5,107.31 23.5,112.24 23.65,112.39 262.25,112.39 263.52,111.12 263.52,3.17 261.62,1.27 93.34,1.27 93.34,1.9 ; 1 cut-out
GND_EARTH on GND (solid shape): 122.3,21.08 120.8,21.08 120.8,22.88 122.3,22.88
GND_EARTH on GND: 121.4,39.08 121.4,5.08 145.4,5.08 145.4,39.08
VCC on VCC: 23.65,1.9 23.5,2.06 23.5,6.99 2.06,6.99 1.9,7.14 1.9,107.16 2.06,107.31 23.5,107.31 23.5,112.24 23.65,112.39 262.25,112.39 263.52,111.12 263.52,3.17 261.62,1.27 93.34,1.27 93.34,1.9

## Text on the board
USER_PART_NUM_TOP: TP6 | TP4 | TP5 | TP2 | TP1 | TP3
User.11: FIGURE | SIZE | 0.33 | 0.787 | 0.965 | 1.905 | 4.0 | DRILL CHART: TOP to BOTTOM | ALL UNITS ARE IN MILLIMETERS | PLATED | NON-PLATED | QTY | 674 | 12 | 194 | 8
